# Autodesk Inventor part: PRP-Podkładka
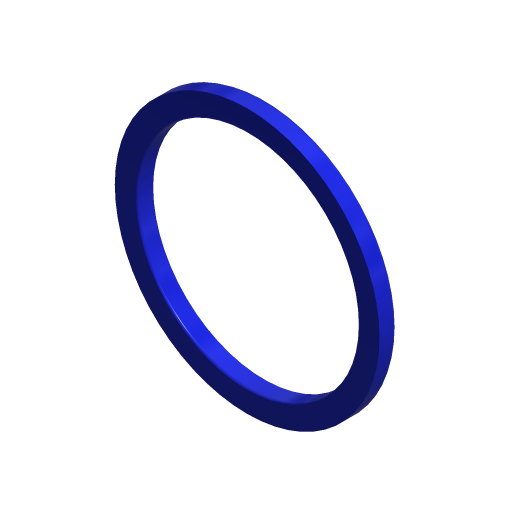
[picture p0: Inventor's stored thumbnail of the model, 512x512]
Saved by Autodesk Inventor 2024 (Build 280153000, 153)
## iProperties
Created: 2023-03
Part Number: PRP-Podkładka
Document SubType Name: Modeling
Designer: Andrzej Jaskulski
Material: Kurs-AJ
Density: 1 g/cm^3
Mass: 0.424834 g
Surface Area: 7.40408 cm^2
Volume: 0.424834 cm^3
Appearance: Niebieska — farba ścienna — lśniąca
Checked By: A.J.
Engr Approved By: Andrzej Jaskulski
Mfg Approved By: Andrzej Jaskulski
Authority: A.J.
Company: ATC
Control State: 0
Master: False
Checked Out: False
Shininess: 0.0
Length Units: 11269
Angle Units: 11279
Time Units: 11290
Mass Units: 11283
Length Display Precision: 3
Angle Display Precision: 2
Compacted: True
Density: 0.0
Volumn: 0.0
Area: 0.0
PropertySet Name: Model Information
Title: A.J.: Kurs R2024-MEP
Author: Andrzej Jaskulski
Revision Number: 1/24
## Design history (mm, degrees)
node "Extrusion1" dims "d2" = 2, "d3" = 0
node "Fillet1" dims "d4" = 0.25, "d5" = 0.5
node "Bryła1"
node "Korpusy bryłowe"
node "Korpusy powierzchniowe"
sketch "Sketch1"
  geometry: C1 r 12.5 at (36, 61); C2 r 15 at (36, 61)
  constraints: 2 centre point, 1 coincident
  dimensions: "d0" = 25 diameter of C1; "d1" = 30 diameter of C2
